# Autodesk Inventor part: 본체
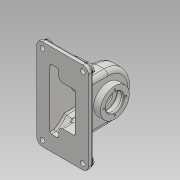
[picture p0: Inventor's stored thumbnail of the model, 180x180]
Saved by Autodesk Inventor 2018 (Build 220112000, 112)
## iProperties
Created: 2024-01
Part Number: 본체
Material: 알루미늄 6061
Document SubType Name: Modeling
Designer: home
Density: 2.7 g/cm^3
Appearance: 기본값
Mass: 914.572 g
Surface Area: 937.064 cm^2
Volume: 338.73 cm^3
Author: home
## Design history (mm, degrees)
sketch "스케치1"
  geometry: L1 (-50, -88)-(50, -88); L2 (50, -88)-(50, 88); L3 (50, 88)-(-50, 88); L4 (-50, 88)-(-50, -88); L5 (-50, -88)-(50, 88); L6 (50, -88)-(-50, 88); 1 further point
  constraints: 12 end point, 2 midpoint, 2 parallel, 1 horizontal, 1 perpendicular
  dimensions: "d0" = 100 distance of L2.end L3.end; "d1" = 176 distance of L1.end L2.end
extrude "돌출1" new body sketch "스케치1" distance "d2" = 9; taper "d3" = 0 deg
node "작업 평면1"
sketch "스케치2"
  geometry: L1 (176, 9)-(176, 0) reference; L2 (176, 0)-(0, 0) reference; L3 (0, 0)-(0, 9) reference; L4 (0, 9)-(176, 9) reference; L5 (42, 9)-(42, 56); L6 (176, 9)-(0, 9) reference; L7 (134, 9)-(134, 56); L8 (134, 9)-(42, 9); A1 r 46 centre (88, 56) between (42, 56) and (134, 56); A2 r 46 centre (88, 56) between (134, 56) and (42, 56); 2 further points
  constraints: 6 end point, 4 point on circle, 2 centre point, 2 point on line, 2 tangent, 1 collinear, 1 midpoint, 1 perpendicular, 1 vertical, 1 vertical alignment
  dimensions: "d5" = 92 diameter of A1; "d6" = 56 distance from line of A1.centre L2
extrude "돌출2" join sketch "스케치2" distance "d7" = 32; taper "d8" = 0 deg
sketch "스케치3"
  geometry: C1 r 28 at (88, 56); A1 r 46 centre (88, 56) between (134, 56) and (42, 56) reference; 1 further point
  constraints: 1 centre point, 1 coincident
  dimensions: "d9" = 56 diameter of C1
extrude "돌출3" join sketch "스케치3" distance "d10" = 13; taper "d11" = 0 deg
sketch "스케치4"
  geometry: L1 (9, -88)-(0, -88) reference; L2 (0, -88)-(0, 88) reference; L3 (0, 88)-(9, 88) reference; L4 (9, 88)-(9, 46) reference; L5 (9, 46)-(9, -46) reference; L6 (9, -46)-(9, -88) reference; L7 (9, 46)-(56, 46) reference; L8 (56, -46)-(9, -46) reference; L9 (0, -67.882)-(0, 67.882); L10 (56, 46)-(9, 46) reference; L11 (56, -46)-(31.39, -46); L12 (9, -46)-(9, 46); L13 (9, 46)-(31.39, 46); L14 (56, 46)-(56, -46); L15 (31.39, -46)-(9, -46); L16 (31.39, 46)-(56, 46); A1 r 46 centre (56, 0) between (56, -46) and (56, 46) reference; A2 r 72 centre (-24, 0) between (0, -67.882) and (31.39, 46); A3 r 72 centre (-24, 0) between (0, 67.882) and (0, -67.882); A4 r 72 centre (-24, 0) between (31.39, 46) and (0, 67.882); 1 further point
  constraints: 14 end point, 8 point on circle, 5 parallel, 3 centre point, 2 horizontal, 2 perpendicular, 2 point on line, 1 horizontal alignment
  dimensions: "d12" = 144 diameter of A2; "d13" = 24 distance from line of L2 A2.centre
  node "절단 모서리 투영2"
extrude "돌출4" join sketch "스케치4" distance "d14" = 32; taper "d15" = 0 deg
sketch "스케치5"
  geometry: L1 (9, -88)-(0, -88) reference; L2 (0, -88)-(0, 88) reference; L3 (0, 88)-(9, 88) reference; L4 (9, 88)-(9, 63.992) reference; L5 (9, 46)-(31.39, 46) reference; L6 (9, 63.992)-(9, 46) reference; L7 (9, -63.992)-(9, -88) reference; L8 (31.39, -46)-(9, -46) reference; L9 (9, -46)-(9, -63.992) reference; L10 (56, -46)-(31.39, -46) reference; L11 (31.39, 46)-(56, 46) reference; C1 r 28 at (56, 0); A1 r 72 centre (-24, 0) between (31.39, 46) and (9, 63.992) reference; A2 r 72 centre (-24, 0) between (9, -63.992) and (31.39, -46) reference; A3 r 72 centre (-24, 0) between (31.39, -46) and (31.39, 46) reference; A4 r 46 centre (56, 0) between (56, -46) and (56, 46) reference; 1 further point
  constraints: 1 centre point, 1 coincident
  dimensions: "d16" = 28 radius of C1
extrude "돌출5" join sketch "스케치5" distance "d17" = 45; taper "d18" = 0 deg
extrude "돌출6" join sketch "스케치4" distance "d19" = 32; taper "d20" = 0 deg
feature "쉘1" dims "d25" = 5
sketch "스케치9"
  geometry: L1 (50, 88)-(50, -88) reference; L2 (50, -88)-(-50, -88) reference; L3 (-50, -88)-(-50, 88) reference; L4 (-50, 88)-(50, 88) reference; L5 (50, 88)-(50, -88) reference; L6 (50, -88)-(-50, -88) reference; L7 (-50, -88)-(-50, 88) reference; L8 (-50, 88)-(50, 88) reference; L9 (-5, -60.869)-(-5, -41) reference; L10 (-27, -60.869)-(-5, -60.869) reference; L11 (-27, 60.869)-(-27, -60.869) reference; L12 (-5, 60.869)-(-27, 60.869) reference; L13 (-5, 41)-(-5, 60.869) reference; L14 (27, 41)-(-5, 41) reference; L15 (27, -41)-(27, 41) reference; L16 (-5, -41)-(27, -41) reference; L17 (45, -83)-(-45, -83) reference; L18 (45, 83)-(45, -83) reference; L19 (-45, 83)-(45, 83) reference; L20 (-45, -83)-(-45, 83) reference; L21 (-7.5, -58.369)-(-7.5, -38.5); L22 (-7.5, -38.5)-(24.5, -38.5); L23 (24.5, -38.5)-(24.5, 38.5); L24 (24.5, 38.5)-(-7.5, 38.5); L25 (-7.5, 38.5)-(-7.5, 58.369); L26 (-7.5, 58.369)-(-24.5, 58.369); L27 (-24.5, 58.369)-(-24.5, -58.369); L28 (-24.5, -58.369)-(-7.5, -58.369); L29 (45, -83)-(45, 83) reference; L30 (45, 83)-(-45, 83) reference; L31 (-45, 83)-(-45, -83) reference; L32 (-45, -83)-(45, -83) reference; L33 (45, -83)-(45, 83) reference; L34 (45, 83)-(-45, 83) reference; L35 (-45, 83)-(-45, -83) reference; L36 (-45, -83)-(45, -83) reference; 1 further point
  constraints: 16 end point, 7 other
  dimensions: "d26" = 2.5 distance between parallel lines of L10 L28
extrude "돌출7" join sketch "스케치9" stored distance "d27" = 32; taper "d28" = 0 deg
sketch "스케치11"
  geometry: L1 (40, 22.131)-(40, 42) reference; L2 (18, 22.131)-(40, 22.131) reference; L3 (18, 143.869)-(18, 22.131) reference; L4 (40, 143.869)-(18, 143.869) reference; L5 (40, 124)-(40, 143.869) reference; L6 (72, 124)-(40, 124) reference; L7 (72, 42)-(72, 124) reference; L8 (40, 42)-(72, 42) reference; L9 (90, 0)-(0, 0) reference; L10 (90, 166)-(90, 0) reference; L11 (0, 166)-(90, 166) reference; L12 (0, 0)-(0, 166) reference; L13 (40, 22.131)-(40, 42) reference; L14 (18, 22.131)-(40, 22.131) reference; L15 (18, 143.869)-(18, 22.131) reference; L16 (40, 143.869)-(18, 143.869) reference; L17 (40, 124)-(40, 143.869) reference; L18 (72, 124)-(40, 124) reference; L19 (72, 42)-(72, 124) reference; L20 (40, 42)-(72, 42) reference; L21 (90, 0)-(0, 0) reference; L22 (90, 166)-(90, 0) reference; L23 (0, 166)-(90, 166) reference; L24 (0, 0)-(0, 166) reference; 1 further point
extrude "돌출8" join sketch "스케치11" distance "d29" = 4; taper "d30" = 0 deg
sketch "스케치13"
  geometry: L1 (-27, 33)-(-27, 79) reference; L2 (-27, 79)-(-40, 79) reference; L3 (-40, 79)-(-40, 33) reference; L4 (-40, 33)-(-27, 33) reference; L5 (40, 33)-(40, 79) reference; L6 (40, 79)-(27, 79) reference; L7 (27, 79)-(27, 33) reference; L8 (27, 33)-(40, 33) reference; L9 (32, 84)-(45, 84) reference; L10 (45, 84)-(45, 28) reference; L11 (45, 28)-(32, 28) reference; L12 (32, 28)-(32, 9) reference; L13 (32, 9)-(50, 9) reference; L14 (50, 9)-(50, 0) reference; L15 (50, 0)-(24.5, 0) reference; L16 (24.5, 0)-(24.5, 97) reference; L17 (24.5, 97)-(5, 97) reference; L18 (5, 97)-(5, 79) reference; L19 (5, 79)-(-24.5, 79) reference; L20 (-24.5, 79)-(-24.5, 0) reference; L21 (-24.5, 0)-(-50, 0) reference; L22 (-50, 0)-(-50, 9) reference; L23 (-50, 9)-(-32, 9) reference; L24 (-32, 9)-(-32, 28) reference; L25 (-32, 28)-(-45, 28) reference; L26 (-45, 28)-(-45, 84) reference; L27 (-45, 84)-(0, 84) reference; L28 (0, 84)-(0, 102) reference; L29 (0, 102)-(32, 102) reference; L30 (32, 102)-(32, 84) reference; L31 (-45, 84)-(-45, 28) reference; L32 (-45, 56)-(45, 56); L33 (-45, 56)-(-45, 73.5); L34 (-45, 73.5)-(-30, 73.5); L35 (-30, 73.5)-(-30, 70.5); L36 (32, 70.126)-(32, 73.5); L37 (32, 84)-(32, 28) reference; L38 (45, 73.5)-(45, 56); L39 (45, 28)-(45, 84) reference; L40 (-30, 70.5)-(30, 70.5); L41 (30, 70.5)-(30, 73.5); L42 (45, 73.5)-(30, 73.5); 1 further point
  constraints: 18 end point, 5 point on line, 2 horizontal, 2 midpoint, 1 collinear, 1 parallel, 1 perpendicular, 1 vertical
  dimensions: "d31" = 35 diameter of L34 L32; "d32" = 29 diameter of L40 L32; "d33" = 15 distance between parallel lines of L33 L35; "d34" = 15 distance between parallel lines of L10 L41
revolve "회전1" sketch "스케치13" stored, may be unused: angle "d35" = 90 deg
fillet "모깎기1" dims "d36" = 11
sketch "스케치15"
  geometry: C1 r 9 at (-39, -77); C2 r 9 at (39, -77); C3 r 9 at (39, 77); C4 r 9 at (-39, 77); A1 r 11 centre (-39, 77) between (-39, 88) and (-50, 77) reference; A2 r 11 centre (-39, -77) between (-50, -77) and (-39, -88) reference; A3 r 11 centre (39, -77) between (39, -88) and (50, -77) reference; A4 r 11 centre (39, 77) between (50, 77) and (39, 88) reference; 1 further point
  constraints: 4 centre point, 4 coincident
  dimensions: "d37" = 9 radius of C1; "d38" = 9 radius of C2; "d39" = 9 radius of C3; "d40" = 9 radius of C4
extrude "돌출9" join sketch "스케치15" distance "d41" = 4; taper "d42" = 0 deg
sketch "스케치16"
  geometry: C1 r 9 at (0, 0) reference; C2 r 9 at (78, 0) reference; C3 r 9 at (78, 154) reference; C4 r 9 at (0, 154) reference; C5 r 9 at (78, 0) reference; 5 further points
  constraints: 4 coincident
hole "구멍1" sketch "스케치16" at (0, 0), (78, 0), (78, 154), (0, 154) diameter "d43" = 9; stored, may be unused: countersink angle "d47" = 90 deg, drill point angle "d49" = 118 deg; dims "d44" = 6, "d45" = 4, "d46" = 2, "d48" = 8
node "작업 평면2"
sketch "스케치17"
  geometry: C1 r 6 at (17, 0); 1 further point
  constraints: 1 centre point, 1 horizontal alignment
  dimensions: "d53" = 12 diameter of C1; "d54" = 17 distance of C1.centre point (0, 0)
extrude "돌출10" join sketch "스케치17" stored distance "d55" = 4; taper "d56" = 0 deg
sketch "스케치18"
  geometry: C1 r 6 at (0, 0) reference; 2 further points
  constraints: 1 coincident
hole "구멍2" sketch "스케치18" at (0, 0) diameter "d57" = 5.188; stored, may be unused: countersink angle "d61" = 90 deg, drill point angle "d63" = 0 deg; dims "d58" = 12, "d59" = 8, "d60" = 2, "d62" = 16
node "작업 평면3"
sketch "스케치19"
  geometry: C1 r 6 at (-17, 0); 1 further point
  constraints: 1 centre point, 1 horizontal alignment
  dimensions: "d65" = 12 diameter of C1; "d66" = 17 distance of point (0, 0) C1.centre
extrude "돌출11" join sketch "스케치19" stored distance "d67" = 4; taper "d68" = 0 deg
sketch "스케치20"
  geometry: C1 r 6 at (0, 0) reference; 2 further points
  constraints: 1 coincident
hole "구멍3" sketch "스케치20" at (0, 0) diameter "d69" = 5.188; stored, may be unused: countersink angle "d73" = 90 deg, drill point angle "d75" = 0 deg; dims "d70" = 12, "d71" = 8, "d72" = 2, "d74" = 16
sketch "스케치21" dims "d76" = 21.5
  geometry: C1 r 17.5 at (0, 0) reference; C2 r 28 at (0, 0) reference; 3 further points
  constraints: 2 vertical alignment, 1 coincident, 2 other
hole "구멍4" sketch "스케치21" at (0, 21.5) diameter "d77" = 3.242; stored, may be unused: countersink angle "d81" = 90 deg, drill point angle "d83" = 118 deg; dims "d78" = 8, "d79" = 8, "d80" = 2, "d82" = 10
node "작업 평면4"
fillet "모깎기4" dims "d89" = 3
fillet "모깎기5" dims "d90" = 8
fillet "모깎기6" dims "d91" = 3
fillet "모깎기7" dims "d92" = 3, "d93" = 0.6
chamfer "모따기1" distance "d94" = 1; stored, may be unused: second distance "d95" = 2, angle "d96" = 45 deg
chamfer "모따기2" distance "d97" = 1; stored, may be unused: second distance "d98" = 2, angle "d99" = 45 deg
fillet "모깎기8" dims "d100" = 7
sketch "스케치22"
  geometry: L1 (-15, -48)-(63, -48) reference; L2 (-26, -42)-(-26, -48) reference; 2 further points
  constraints: 1 other
  dimensions: "d101" = 40 distance from line of L1 point (24, -8); "d102" = 50 distance from line of L2 point (24, -8)
feature "엠보싱1" sketch "스케치22" dims "d8" = 0, "d103" = 0.5, "d104" = 0
fillet "모깎기9" dims "d105" = 3, "d107" = 8
fillet "모깎기10" dims "d106" = 8
fillet "모깎기11" dims "d108" = 3
fillet "모깎기12" dims "d109" = 8
node "솔리드1"
pattern_circular "원형 패턴1" dims angle "d85" = 360 deg
mirror "미러1"
node "투영된 루프1"
node "투영된 루프2"
node "투영된 루프3"
node "투영된 루프4"
node "절단 모서리 투영1"
node "절단 모서리 투영3"
node "절단 모서리 투영6"
node "절단 모서리 투영7"
node "절단 모서리 투영9"
other parameters: "d52" = -106, "d64" = -88, "d87" = -45
